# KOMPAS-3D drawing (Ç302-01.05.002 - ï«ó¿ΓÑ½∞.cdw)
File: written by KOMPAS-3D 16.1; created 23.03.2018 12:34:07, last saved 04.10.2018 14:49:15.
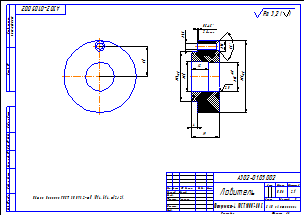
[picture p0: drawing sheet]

Sheet 1: A3, landscape

Title block, sheet 1: name: Ловитель; designation: А302-01.05.002; material: Фторопласт-4  ГОСТ 10007-80 Е; mass: 0,06; scale: 2:1; sheets: 1; organisation: ЗАО «Астерион»; sheet format: A3; stored path: \\192.168.87.28\Konstructor_doc\Мембранные насосы\Мембранный электропривод\А302-00.00.000 - ASTRA-302 (МЭ200)\Чертежи\А302-00.05.002 - Ловитель.cdw; drawn by: Милов; technical control: Лучихин

Views: Вид 1, Местный разрез 1, Снизу, Проекционный вид 2, Вид:1, Вид:2
Referenced files in \\192.168.87.28\Konstructor_doc\Мембранные насосы\Мембранный электропривод\А302-00.00.000 - ASTRA-302 (МЭ200)\3Д ПВХ\Отработка\: А302-01.05.002 - Ловитель.m3d
Referenced files in Z:\Мембранные насосы\Мембранный электропривод\А302-00.00.000 - ASTRA-302 (МЭ200)\3Д\: А302-00.05.002 - Ловитель.m3d
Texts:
  Общие допуски ГОСТ 30893.2-mK (H14, h14,  t2/2).
  Ra 3,2
  Ra 3,2 ( )
Dimensions and other numbers on the sheet: 20; 21; 12; 19; 34; 50; 2,5; 4,3; 7,3; 4; 0,5; 2 фаски; 2:1; 1; 0,06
